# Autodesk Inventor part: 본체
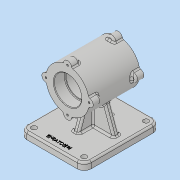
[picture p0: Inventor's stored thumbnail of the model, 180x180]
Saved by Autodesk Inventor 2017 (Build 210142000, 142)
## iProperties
Part Number: 본체
Material: 일반
Document SubType Name: Modeling
Designer: MRC
Density: 1 g/cm^3
Appearance: 기본값
Author: MRC
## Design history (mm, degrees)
sketch "스케치1"
  geometry: L1 (0, 0)-(0, 43.5); L2 (37, 43.5)-(23.5, 43.5); L3 (23.5, 43.5)-(23.5, 24.5); L4 (23.5, 24.5)-(21, 24.5); L5 (21, 24.5)-(21, 0); L6 (21, 0)-(37, 0); L7 (37, 0)-(37, 43.5)
  constraints: 14 end point, 5 perpendicular, 2 horizontal alignment, 1 horizontal, 1 vertical
  dimensions: "d0" = 43.5 distance of L1.start L1.end; "d1" = 47 diameter of L3 L1; "d2" = 42 diameter of L5 L1; "d3" = 74 diameter of L7 L1; "d4" = 19 distance of L2.end L3.end
revolve "회전1" sketch "스케치1" stored, may be unused: angle "d5" = 90 deg
sketch "스케치2"
  geometry: C1 r 7 at (0, 37); 2 further points
  constraints: 2 vertical alignment, 1 centre point, 1 other
  dimensions: "d6" = 14 diameter of C1
extrude "돌출1" join sketch "스케치2" distance "d7" = 14; taper "d8" = 0 deg
sketch "스케치3"
  geometry: A1 r 7 centre (0, 0) between (6.969, -0.662) and (-6.969, -0.662) reference; 2 further points
  constraints: 1 coincident
hole "구멍1" sketch "스케치3" at (0, 0) diameter "d9" = 3.242; stored, may be unused: countersink angle "d13" = 90 deg, drill point angle "d15" = 118 deg; dims "d10" = 8, "d11" = 4, "d12" = 2, "d14" = 10
fillet "모깎기1" dims "d19" = 1
chamfer "모따기1" distance "d20" = 1; stored, may be unused: second distance "d21" = 2, angle "d22" = 45 deg
fillet "모깎기2" dims "d23" = 3
fillet "모깎기3" dims "d24" = 3
node "작업 평면1"
sketch "스케치4"
  geometry: L1 (55, 70)-(-55, 70); L2 (-55, 70)-(-55, -60); L3 (-55, -60)-(55, -60); L4 (55, -60)-(55, 70); 2 further points
  constraints: 8 end point, 2 parallel, 1 horizontal, 1 midpoint, 1 perpendicular, 1 vertical alignment
  dimensions: "d26" = 130 distance of L1.end L2.end; "d27" = 110 distance of L2.end L3.end; "d28" = 70 distance from line of point (0, 0) L1
extrude "돌출2" join sketch "스케치4" distance "d29" = 12; taper "d30" = 0 deg
fillet "모깎기4" dims "d31" = 12
sketch "스케치5"
  geometry: C1 r 4.5 at (43, -58); A1 r 12 centre (43, -58) between (43, -70) and (55, -58) reference; 1 further point
  constraints: 1 centre point, 1 concentric
  dimensions: "d32" = 9 diameter of C1
extrude "돌출3" cut sketch "스케치5" stored distance "d33" = 12; taper "d34" = 0 deg
sketch "스케치6"
  geometry: L1 (-5, -5)-(5, -5); L2 (5, -5)-(5, 5); L3 (5, 5)-(-5, 5); L4 (-5, 5)-(-5, -5); L5 (-5, -5)-(5, 5); L6 (5, -5)-(-5, 5); 1 further point
  constraints: 12 end point, 2 midpoint, 2 parallel, 1 horizontal, 1 perpendicular
  dimensions: "d41" = 10 distance of L3.end L2.end; "d42" = 10 distance of L2.end L1.end
extrude "돌출4" join sketch "스케치6" stored distance "d43" = 12; taper "d44" = 0 deg
sketch "스케치7"
  geometry: L1 (41, -70)-(30.319, -40.654); L2 (43, -70)-(55, -70) reference; L3 (55, -70)-(55, -82) reference; 1 further point
  constraints: 2 end point, 1 point on line
  dimensions: "d45" = 14 distance from line of L1.start L3; "d46" = 110 deg angle of L1 L2
feature "리브1" sketch "스케치7" dims "d47" = 1, "d48" = 10, "d49" = 0, "d50" = 0, "d51" = 1, "d52" = 1
sketch "스케치8"
  geometry: L1 (-70, -30)-(-47.073, -21.655); L2 (-70, -48)-(-70, 58) reference; 1 further point
  constraints: 2 end point, 1 point on line
  dimensions: "d53" = 30 vertical distance of L1.start point (0, 0); "d54" = 110 deg angle of L1 L2
feature "리브2" sketch "스케치8" dims "d55" = 1, "d56" = 10, "d57" = 0, "d58" = 0, "d59" = 1, "d60" = 1
sketch "스케치9"
  geometry: 2 further points
  constraints: 1 vertical alignment, 1 other
  dimensions: "d61" = 58 distance of point (0, -58) point (0, 0)
feature "엠보싱1" sketch "스케치9" dims "d0" = 43.5, "d1" = 47, "d2" = 42, "d3" = 74, "d4" = 19, "d9" = 3.242, "d62" = 0.5, "d63" = 0
fillet "모깎기5" dims "d64" = 3
fillet "모깎기6" dims "d65" = 3
node "솔리드1"
pattern_circular "원형 패턴1" dims angle "d17" = 360 deg
mirror "미러1"
pattern_linear "직사각형 패턴1" dims "d37" = 106, "d40" = 86
mirror "미러2"
mirror "미러3"
other parameters: "d25" = -82
